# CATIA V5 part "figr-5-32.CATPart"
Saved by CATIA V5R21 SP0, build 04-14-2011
Part number: Part1
Bounding box of the stored display mesh (mm): x -32.491 to 32.491, y -32.393 to 32.393, z 0 to 85.656
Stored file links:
  D:\CATIA V5R21 E-RESOURCES\CATIA-V5R21\catia-v5r21-prt\c05-catia-v5r20-prt\catia-v5r21-figr-5-32.CATPart
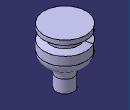
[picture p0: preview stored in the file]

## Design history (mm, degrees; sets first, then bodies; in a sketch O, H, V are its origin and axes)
Body1 (main body)
  Sketch1 on yz-plane, origin (0, 0, 0), H (0, 1, 0), V (0, 0, 1)
    axis line L1 (0, 0) -> (0, 100.0993)
    line L2 (0, 0) -> (13.3295, 0)
    line L3 (13.3295, 0) -> (13.3295, 19.6564)
    arc A1 centre (31.7623, 19.6564) radius 18.4328 from (13.3295, 19.6564) to (23.518, 36.1427) cw
    arc A2 centre (16.25, 50.6768) radius 16.25 from (23.518, 36.1427) to (32.5, 50.6768) ccw
    line L4 (32.5, 50.6768) -> (32.5, 85.6563)
    line L5 (32.5, 85.6563) -> (0, 85.6563)
    point P9 (0, 85.6563)
    line L6 (0, 85.6563) -> (0, 0)
    "Radius" L4 L1 = 32.5
    vertical: L1 V, L3 V, L4 V
    horizontal: L2 H, L5 H
    tangency: A1 L3, A2 L1, A2 A1, L4 A2, L6 A2
    coincidence: P9 L1
  Shaft1: profile Sketch1, axis Sketch1.L1, angle 360
  Sketch2 on yz-plane, origin (0, 0, 0), H (0, 1, 0), V (0, 0, 1)
    axis line L1 (0, 0) -> (0, 91.1904)
    point P1 (0, 0)
    point P2 (0, 91.1904)
    line L2 (32.5, 78.7512) -> (21.4593, 75.7196)
    line L3 (21.4593, 75.7196) -> (21.4593, 66.4534)
    line L4 (21.4593, 66.4534) -> (32.5, 63.9927)
    line L5 (32.5, 63.9927) -> (32.5, 78.7512)
    coincidence: P1 H, P2 V
    vertical: L1 V, L3 V, L5 V
  Groove1: profile Sketch2, axis Sketch2.L1, angle 360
